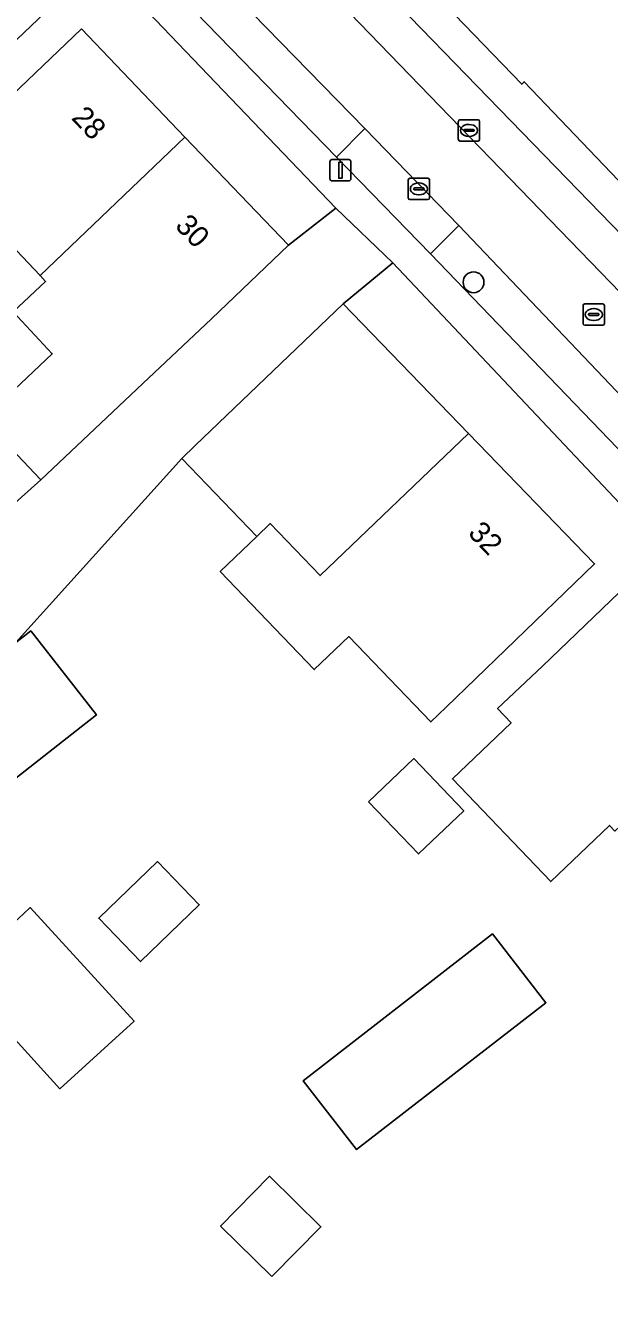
# Model space of a CAD drawing. Extents: x 161772 to 163126, y 383092 to 383917.
# Drawn here: x 162169.5 to 162196.9, y 383341.2 to 383401.8 of the extents above; entities that cross this region are included whole.
import ezdxf

# ---------------------------------------------------------------- set-up
doc = ezdxf.new("R2010")
doc.units = 0
for name, color, linetype in [('IMGEO_Boom', 7, 'Continuous'), ('IMGEO_Erf', 7, 'Continuous'), ('IMGEO_Kolk', 7, 'Continuous'), ('IMGEO_Lichtmast', 7, 'Continuous'), ('IMGEO_Pand', 7, 'Continuous'), ('IMGEO_Pand_nummerreeks', 7, 'Continuous'), ('IMGEO_Parkeervlak_open', 7, 'Continuous'), ('IMGEO_Rijbaan_lokaal_open', 7, 'Continuous'), ('IMGEO_Rioolput', 7, 'Continuous'), ('IMGEO_Voetpad_gesloten', 7, 'Continuous'), ('IMGEO_Voetpad_open', 7, 'Continuous')]:
    doc.layers.add(name, color=color, linetype=linetype)

msp = doc.modelspace()

# ---------------------------------------------------------------- linework, layer by layer
at = {"layer": 'IMGEO_Boom'}
msp.add_circle((162190.5, 383389.8), 0.489, dxfattribs=at)
at = {"layer": 'IMGEO_Erf'}
for points in [[(162168.477, 383398.244), (162172.089, 383401.7), (162176.949, 383396.622), (162181.81, 383391.543), (162184.032, 383393.274), (162150.539, 383428.274)], [(162167.165, 383425.116), (162173.798, 383418.361), (162173.894, 383418.482), (162182.621, 383409.404), (162182.533, 383409.335), (162187.734, 383404.146), (162187.816, 383404.232), (162192.761, 383399.098), (162192.872, 383399.214), (162225.52, 383365.058), (162237.143, 383353.041), (162243.372, 383346.601), (162247.147, 383349.174), (162245.995, 383349.427), (162240.626, 383355.049), (162246.15, 383358.588), (162249.06, 383360.453)], [(162167.466, 383383.372), (162170.723, 383386.441), (162168.886, 383388.407), (162170.408, 383389.842), (162170.152, 383390.116), (162168.195, 383392.17)], [(162234.371, 383341.095), (162232.967, 383342.555), (162231.771, 383343.74), (162215.237, 383360.897), (162198.256, 383378.698), (162198.139, 383378.591), (162186.711, 383390.706), (162184.382, 383388.793), (162190.267, 383382.698), (162196.181, 383376.573), (162189.213, 383369.844), (162188.492, 383369.148), (162184.644, 383373.162), (162183.022, 383371.608), (162178.603, 383376.219), (162180.318, 383377.863), (162176.804, 383381.529), (162168.993, 383372.86), (162169.709, 383373.421), (162172.791, 383369.483), (162172.075, 383368.922), (162166.358, 383364.447)], [(162165.298, 383376.157), (162170.177, 383380.526), (162167.95, 383382.864)], [(162169.358, 383360.126), (162169.69, 383360.429), (162174.561, 383355.097), (162171.082, 383351.92), (162168.818, 383354.399)]]:
    msp.add_lwpolyline(points, dxfattribs=at)
for points in [[(162159.22, 383408.206), (162162.832, 383411.663), (162166.929, 383407.383), (162171.026, 383403.102), (162167.414, 383399.646), (162166.683, 383398.946), (162160.845, 383393.358), (162158.82, 383395.473), (162160.105, 383396.703), (162158.017, 383398.885), (162155.862, 383401.137), (162154.536, 383399.867), (162153.625, 383400.819), (162152.61, 383401.88), (162153.316, 383402.556)], [(162194.119, 383361.649), (162189.504, 383366.474), (162192.26, 383369.109), (162191.627, 383369.786), (162193.73, 383371.769), (162197.341, 383375.226), (162202.851, 383369.47), (162199.239, 383366.013), (162197.138, 383364.023), (162196.882, 383364.291)], [(162185.569, 383365.404), (162187.688, 383367.432), (162190.038, 383364.977), (162187.919, 383362.949)], [(162174.864, 383357.898), (162172.903, 383359.928), (162175.658, 383362.59), (162177.62, 383360.56)], [(162182.5, 383352.298), (162191.388, 383359.191), (162193.894, 383355.96), (162185.005, 383349.067)], [(162181.033, 383343.098), (162178.622, 383345.468), (162180.923, 383347.81), (162183.334, 383345.441)]]:
    msp.add_lwpolyline(points, close=True, dxfattribs=at)
at = {"layer": 'IMGEO_Kolk'}
for p, q in [((162189.784, 383396.506), (162189.784, 383397.358)), ((162189.859, 383397.432), (162190.711, 383397.432)), ((162190.043, 383396.926), (162190.043, 383396.938)), ((162190.481, 383396.889), (162190.083, 383396.889)), ((162190.086, 383396.975), (162190.484, 383396.975)), ((162190.272, 383397.212), (162190.297, 383397.212)), ((162190.527, 383396.938), (162190.527, 383396.926)), ((162190.785, 383397.358), (162190.785, 383396.506)), ((162190.711, 383396.432), (162189.859, 383396.432)), ((162190.295, 383396.652), (162190.27, 383396.652)), ((162187.431, 383393.76), (162187.431, 383394.612)), ((162187.506, 383394.686), (162188.358, 383394.686)), ((162187.919, 383394.466), (162187.944, 383394.466)), ((162188.432, 383394.612), (162188.432, 383393.76)), ((162187.69, 383394.18), (162187.69, 383394.192)), ((162188.128, 383394.143), (162187.73, 383394.143)), ((162187.733, 383394.229), (162188.131, 383394.229)), ((162187.942, 383393.906), (162187.917, 383393.906)), ((162188.174, 383394.192), (162188.174, 383394.18)), ((162188.358, 383393.686), (162187.506, 383393.686))]:
    msp.add_line(p, q, dxfattribs=at)
for points in [[(162189.784, 383396.506), (162189.784, 383397.358)], [(162189.859, 383397.432), (162190.711, 383397.432)], [(162190.785, 383397.358), (162190.785, 383396.506)], [(162190.711, 383396.432), (162189.859, 383396.432)], [(162187.431, 383393.76), (162187.431, 383394.612)], [(162187.506, 383394.686), (162188.358, 383394.686)], [(162188.432, 383394.612), (162188.432, 383393.76)], [(162188.358, 383393.686), (162187.506, 383393.686)]]:
    msp.add_lwpolyline(points, dxfattribs=at)
for centre, radius, start, end in [((162189.861, 383397.356), 0.0765, 91.55205, 178.44795), ((162189.861, 383397.356), 0.0765, 91.55205, 178.44795), ((162190.083, 383396.935), 0.0403, 85.87752, 175.75265), ((162190.08, 383396.925), 0.0366, 178.93798, 274.71019), ((162190.484, 383396.932), 0.043, 264.86636, 352.45326), ((162190.488, 383396.937), 0.0386, 1.73085, 96.63898), ((162190.709, 383397.356), 0.0765, 1.55205, 88.44795), ((162190.709, 383397.356), 0.0765, 1.55205, 88.44795), ((162189.861, 383396.508), 0.0765, 181.55205, 268.44795), ((162189.861, 383396.508), 0.0765, 181.55205, 268.44795), ((162190.709, 383396.508), 0.0765, 271.55205, 358.44795), ((162190.709, 383396.508), 0.0765, 271.55205, 358.44795), ((162187.508, 383394.61), 0.0765, 91.55205, 178.44795), ((162187.508, 383394.61), 0.0765, 91.55205, 178.44795), ((162188.356, 383394.61), 0.0765, 1.55205, 88.44795), ((162188.356, 383394.61), 0.0765, 1.55205, 88.44795), ((162187.73, 383394.189), 0.0403, 85.87752, 175.75265), ((162187.727, 383394.179), 0.0366, 178.93798, 274.71019), ((162188.131, 383394.186), 0.043, 264.86636, 352.45326), ((162188.135, 383394.191), 0.0386, 1.73085, 96.63898), ((162187.508, 383393.762), 0.0765, 181.55205, 268.44795), ((162187.508, 383393.762), 0.0765, 181.55205, 268.44795), ((162188.356, 383393.762), 0.0765, 271.55205, 358.44795), ((162188.356, 383393.762), 0.0765, 271.55205, 358.44795)]:
    msp.add_arc(centre, radius, start, end, dxfattribs=at)
for centre, major_axis, ratio, start_param, end_param in [((162190.271, 383396.932), (-0.387, 0.002), 0.722429, 4.712389, 7.853982), ((162190.296, 383396.932), (-0.39, 0.002), 0.717154, 1.570796, 4.712389), ((162187.918, 383394.186), (-0.387, 0.002), 0.722429, 4.712389, 7.853982), ((162187.943, 383394.186), (-0.39, 0.002), 0.717154, 1.570796, 4.712389)]:
    msp.add_ellipse(centre, major_axis=major_axis, ratio=ratio, start_param=start_param, end_param=end_param, dxfattribs=at)
at = {"layer": 'IMGEO_Lichtmast'}
for p, q in [((162183.753, 383394.658), (162183.753, 383395.458)), ((162183.753, 383395.458), (162183.753, 383394.658)), ((162183.853, 383395.558), (162184.643, 383395.558)), ((162184.643, 383395.558), (162183.853, 383395.558)), ((162184.743, 383395.458), (162184.743, 383394.658)), ((162184.743, 383394.658), (162184.743, 383395.458)), ((162184.643, 383394.558), (162183.853, 383394.558)), ((162183.853, 383394.558), (162184.643, 383394.558))]:
    msp.add_line(p, q, dxfattribs=at)
msp.add_lwpolyline([(162184.173, 383395.433), (162184.323, 383395.433), (162184.323, 383394.683), (162184.173, 383394.683), (162184.173, 383395.433)], dxfattribs=at)
for centre, start, end in [((162183.853, 383395.458), 90, 180), ((162183.853, 383395.458), 90, 180), ((162184.643, 383395.458), 0, 90), ((162184.643, 383395.458), 360, 90), ((162183.853, 383394.658), 180, 270), ((162183.853, 383394.658), 180, 270), ((162184.643, 383394.658), 270, 0), ((162184.643, 383394.658), 270, 0)]:
    msp.add_arc(centre, 0.1, start, end, dxfattribs=at)
at = {"layer": 'IMGEO_Pand'}
for points in [[(162171.026, 383403.102), (162166.929, 383407.383), (162159.445, 383400.223), (162158.017, 383398.885), (162160.105, 383396.703), (162158.82, 383395.473), (162160.845, 383393.358), (162166.683, 383398.946), (162167.414, 383399.646)], [(162176.949, 383396.622), (162172.089, 383401.7), (162168.477, 383398.244), (162165.273, 383395.238), (162157.565, 383387.973), (162160.488, 383384.905), (162168.195, 383392.17), (162170.152, 383390.116)], [(162176.949, 383396.622), (162170.152, 383390.116), (162170.408, 383389.842), (162168.886, 383388.407), (162170.723, 383386.441), (162167.466, 383383.372), (162167.95, 383382.864), (162170.177, 383380.526), (162174.977, 383385.05), (162178.198, 383388.086), (162181.81, 383391.543)], [(162190.267, 383382.698), (162184.382, 383388.793), (162177.434, 383382.133), (162176.804, 383381.529), (162180.318, 383377.863), (162180.948, 383378.467), (162183.291, 383376.022)], [(162196.181, 383376.573), (162190.267, 383382.698), (162183.291, 383376.022), (162180.948, 383378.467), (162180.318, 383377.863), (162178.603, 383376.219), (162183.022, 383371.608), (162184.644, 383373.162), (162188.492, 383369.148), (162189.213, 383369.844)], [(162202.851, 383369.47), (162197.341, 383375.226), (162193.73, 383371.769), (162191.627, 383369.786), (162192.26, 383369.109), (162189.504, 383366.474), (162194.119, 383361.649), (162196.882, 383364.291), (162197.138, 383364.023), (162199.239, 383366.013)], [(162172.075, 383368.922), (162172.791, 383369.483), (162169.709, 383373.421), (162168.993, 383372.86), (162168.206, 383372.243), (162163.278, 383368.383), (162165.491, 383365.556), (162166.358, 383364.447)], [(162185.569, 383365.404), (162187.919, 383362.949), (162190.038, 383364.977), (162187.688, 383367.432)], [(162175.658, 383362.59), (162172.903, 383359.928), (162174.864, 383357.898), (162177.62, 383360.56)], [(162169.69, 383360.429), (162169.358, 383360.126), (162166.807, 383357.796), (162165.882, 383356.951), (162168.488, 383354.098), (162168.818, 383354.399), (162171.082, 383351.92), (162174.561, 383355.097)], [(162185.005, 383349.067), (162193.894, 383355.96), (162191.388, 383359.191), (162182.5, 383352.298)], [(162181.033, 383343.098), (162183.334, 383345.441), (162180.923, 383347.81), (162178.622, 383345.468)]]:
    msp.add_lwpolyline(points, close=True, dxfattribs=at)
at = {"layer": 'IMGEO_Parkeervlak_open'}
for points in [[(162228.36, 383359.913), (162202.24, 383387.094), (162166.479, 383423.941), (162146.078, 383445.121), (162144.674, 383443.797), (162227.035, 383358.663)], [(162150.325, 383430.382), (162184.058, 383395.679), (162185.398, 383397.017), (162162.314, 383420.669), (162151.652, 383431.699)]]:
    msp.add_lwpolyline(points, close=True, dxfattribs=at)
msp.add_lwpolyline([(162233.434, 383344.78), (162235.003, 383344.698), (162235.652, 383344.393), (162235.904, 383344.593), (162198.133, 383383.722), (162189.805, 383392.461), (162188.472, 383391.139), (162232.741, 383345.129)], dxfattribs=at)
at = {"layer": 'IMGEO_Rijbaan_lokaal_open'}
for points in [[(162229.084, 383356.526), (162227.035, 383358.663), (162144.674, 383443.797), (162139.993, 383448.624), (162123.379, 383465.784), (162118.063, 383471.34), (162114.715, 383469.726), (162115.405, 383468.922), (162119.726, 383464.542), (162135.053, 383448.745), (162139.521, 383444.123), (162139.588, 383444.181), (162148.747, 383434.702), (162151.652, 383431.699), (162162.314, 383420.669), (162185.398, 383397.017), (162189.805, 383392.461), (162198.133, 383383.722), (162235.904, 383344.593), (162238.48, 383346.724)], [(162184.382, 383388.793), (162186.711, 383390.706), (162184.032, 383393.274), (162181.81, 383391.543), (162178.198, 383388.086), (162174.977, 383385.05), (162170.177, 383380.526), (162165.298, 383376.157), (162166.231, 383374.982), (162166.127, 383374.899), (162168.206, 383372.243), (162168.993, 383372.86), (162176.804, 383381.529), (162177.434, 383382.133)]]:
    msp.add_lwpolyline(points, close=True, dxfattribs=at)
at = {"layer": 'IMGEO_Rioolput'}
for p, q in [((162195.643, 383387.858), (162195.643, 383388.71)), ((162195.718, 383388.784), (162196.57, 383388.784)), ((162196.131, 383388.564), (162196.156, 383388.564)), ((162196.644, 383388.71), (162196.644, 383387.858)), ((162196.57, 383387.784), (162195.718, 383387.784)), ((162195.902, 383388.278), (162195.902, 383388.29)), ((162196.34, 383388.241), (162195.942, 383388.241)), ((162195.945, 383388.327), (162196.343, 383388.327)), ((162196.154, 383388.004), (162196.129, 383388.004)), ((162196.386, 383388.29), (162196.386, 383388.278))]:
    msp.add_line(p, q, dxfattribs=at)
for points in [[(162195.643, 383387.858), (162195.643, 383388.71)], [(162195.718, 383388.784), (162196.57, 383388.784)], [(162196.644, 383388.71), (162196.644, 383387.858)], [(162196.57, 383387.784), (162195.718, 383387.784)]]:
    msp.add_lwpolyline(points, dxfattribs=at)
for centre, radius, start, end in [((162195.72, 383388.708), 0.0765, 91.55205, 178.44795), ((162195.72, 383388.708), 0.0765, 91.55205, 178.44795), ((162196.568, 383388.708), 0.0765, 1.55205, 88.44795), ((162196.568, 383388.708), 0.0765, 1.55205, 88.44795), ((162195.72, 383387.86), 0.0765, 181.55205, 268.44795), ((162195.72, 383387.86), 0.0765, 181.55205, 268.44795), ((162195.942, 383388.287), 0.0403, 85.87752, 175.75265), ((162195.939, 383388.277), 0.0366, 178.93798, 274.71019), ((162196.343, 383388.284), 0.043, 264.86636, 352.45326), ((162196.347, 383388.289), 0.0386, 1.73085, 96.63898), ((162196.568, 383387.86), 0.0765, 271.55205, 358.44795), ((162196.568, 383387.86), 0.0765, 271.55205, 358.44795)]:
    msp.add_arc(centre, radius, start, end, dxfattribs=at)
for centre, major_axis, ratio, start_param, end_param in [((162196.13, 383388.284), (-0.387, 0.002), 0.722429, 4.712389, 7.853982), ((162196.155, 383388.284), (-0.39, 0.002), 0.717154, 1.570796, 4.712389)]:
    msp.add_ellipse(centre, major_axis=major_axis, ratio=ratio, start_param=start_param, end_param=end_param, dxfattribs=at)
at = {"layer": 'IMGEO_Voetpad_gesloten'}
for points in [[(162113.593, 383471.954), (162110.865, 383472.685), (162104.678, 383474.608), (162100.337, 383471.381), (162104.903, 383470.142), (162107.132, 383469.149), (162111.823, 383466.516), (162117.208, 383462.523), (162117.429, 383462.692), (162125.07, 383455.226), (162124.921, 383455.092), (162150.594, 383428.39), (162150.539, 383428.274), (162184.032, 383393.274), (162186.711, 383390.706), (162198.139, 383378.591), (162198.256, 383378.698), (162215.237, 383360.897), (162231.771, 383343.74), (162232.967, 383342.555), (162234.371, 383341.095)], [(162232.741, 383345.129), (162188.472, 383391.139), (162184.058, 383395.679), (162150.325, 383430.382), (162147.38, 383433.399), (162138.229, 383442.804), (162138.751, 383443.331), (162134.258, 383447.982), (162135.053, 383448.745), (162119.726, 383464.542), (162118.937, 383463.776), (162114.594, 383468.182), (162115.405, 383468.922), (162114.715, 383469.726)], [(162238.48, 383346.724), (162239.996, 383345.054), (162240.594, 383344.436), (162243.372, 383346.601), (162237.143, 383353.041), (162225.52, 383365.058), (162192.872, 383399.214), (162192.761, 383399.098), (162187.816, 383404.232), (162187.734, 383404.146), (162182.533, 383409.335), (162182.621, 383409.404), (162173.894, 383418.482), (162173.798, 383418.361), (162167.165, 383425.116), (162167.143, 383425.007), (162164.384, 383427.827), (162164.511, 383427.931), (162146.748, 383446.299), (162124.151, 383469.777)], [(162126.398, 383465.384), (162141.362, 383449.954), (162146.078, 383445.121), (162166.479, 383423.941), (162202.24, 383387.094), (162228.36, 383359.913), (162230.382, 383357.811), (162237.721, 383350.184)]]:
    msp.add_lwpolyline(points, dxfattribs=at)
at = {"layer": 'IMGEO_Voetpad_open'}
msp.add_lwpolyline([(162189.805, 383392.461), (162185.398, 383397.017), (162184.058, 383395.679), (162188.472, 383391.139)], close=True, dxfattribs=at)

# ---------------------------------------------------------------- texts
at = {"layer": 'IMGEO_Pand_nummerreeks'}
for s, rotation, p in [('28', 313.74349, (162171.58, 383397.488)), ('30', 313.74349, (162176.441, 383392.409)), ('32', 313.74512, (162190.194, 383377.984))]:
    msp.add_text(s, height=1, rotation=rotation, dxfattribs=at).set_placement(p)

doc.saveas('drawing.dxf')
